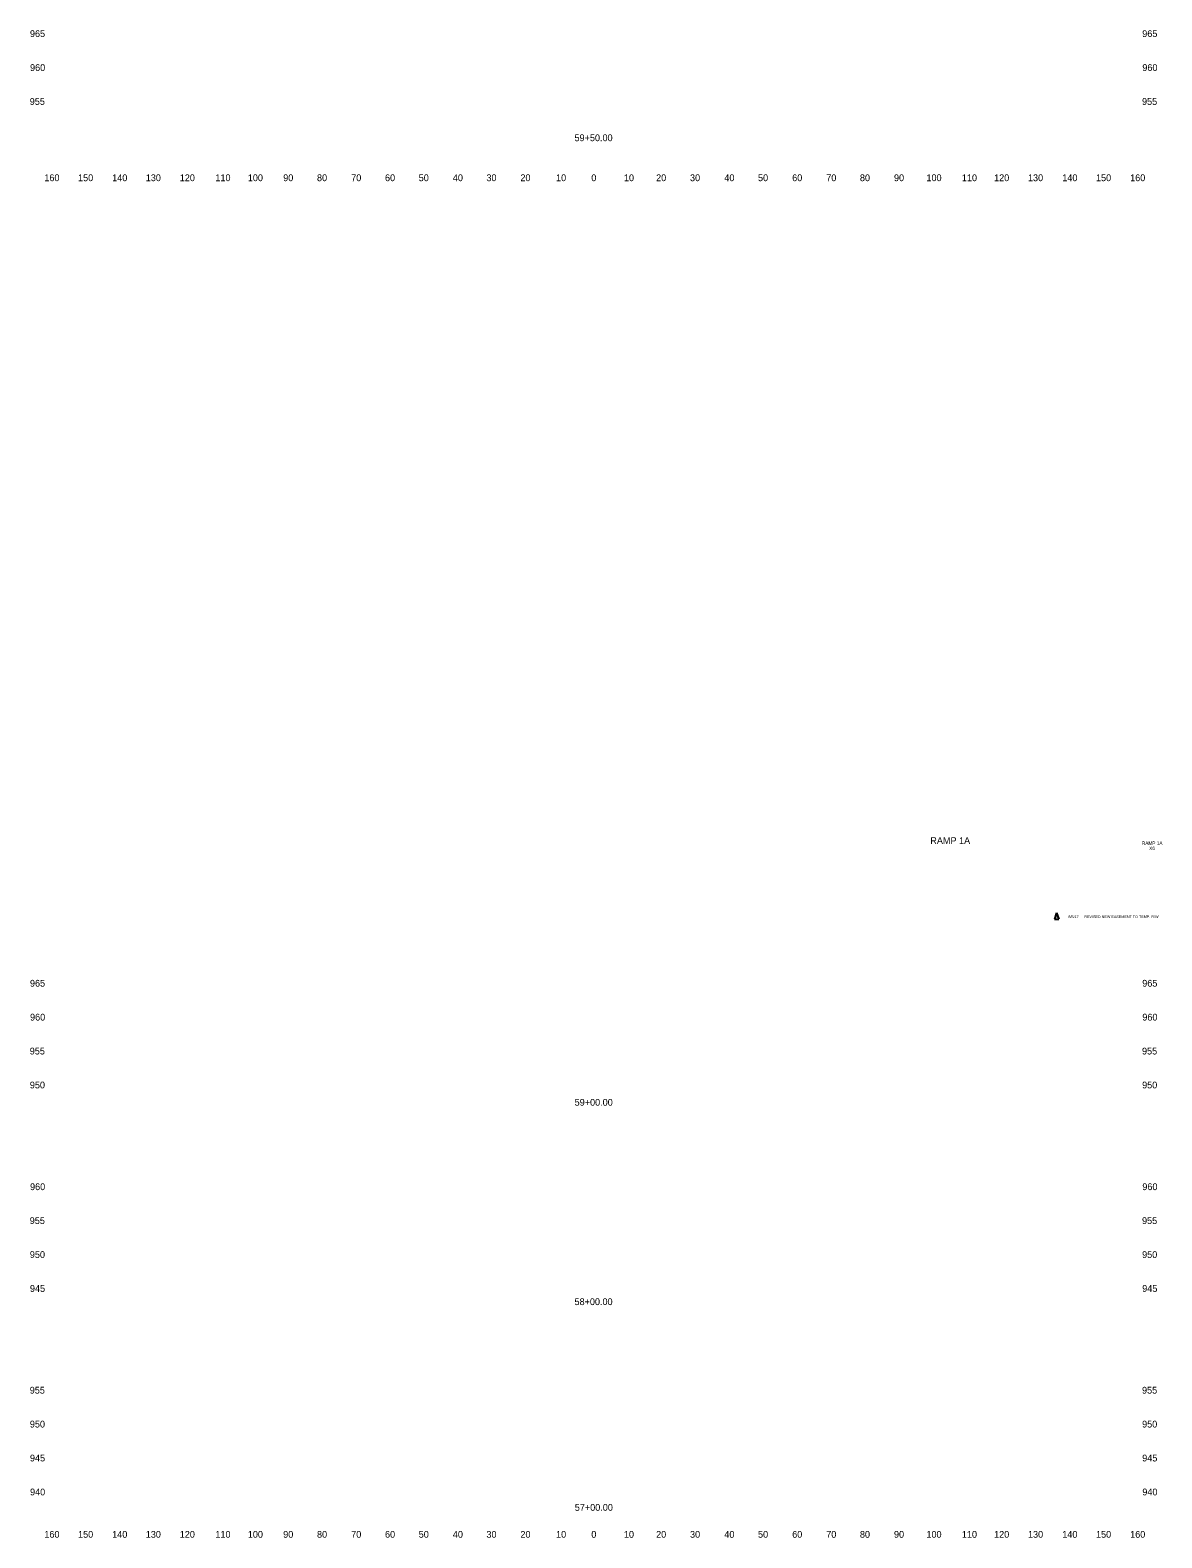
# Model space of a CAD drawing. Extents: x 4994 to 6873, y 4997 to 8804.
# Drawn here: x 4993.9 to 5327.4, y 6997.5 to 7442 of the extents above; entities that cross this region are included whole.
import ezdxf

# ---------------------------------------------------------------- set-up
doc = ezdxf.new("R2010")
doc.units = 0
for name, color, linetype in [('RD_SHT_ID', 7, 'Continuous'), ('RD_SHT_TX', 7, 'Continuous'), ('RD_XS_TX_Offset', 7, 'Continuous'), ('RD_XS_TX_Station', 7, 'Continuous')]:
    doc.layers.add(name, color=color, linetype=linetype)

msp = doc.modelspace()

# ---------------------------------------------------------------- linework, layer by layer
at = {"layer": 'RD_SHT_TX'}
for p, q in [((5296.41, 7181.77), (5295.76, 7179.94)), ((5295.76, 7179.94), (5297.05, 7179.94)), ((5296.41, 7181.77), (5297.05, 7179.94))]:
    msp.add_line(p, q, dxfattribs=at)

# ---------------------------------------------------------------- texts
at = {"layer": 'RD_SHT_ID'}
for s, height, p in [('RAMP 1A', 2, (5259.21, 7202.06)), ('RAMP 1A', 1, (5321.57, 7201.8)), ('X6', 1, (5323.71, 7200.3))]:
    msp.add_text(s, height=height, dxfattribs=at).set_placement(p)
at = {"layer": 'RD_SHT_TX'}
for s, p in [('1', (5296.41, 7180.24)), ('6/5/17', (5299.89, 7180.21)), ('REVISED NEW EASEMENT TO TEMP. R/W', (5304.6, 7180.21))]:
    msp.add_text(s, height=0.792, dxfattribs=at).set_placement(p)
at = {"layer": 'RD_XS_TX_Offset'}
for s, p in [('965', (4993.86, 7440)), ('965', (5321.66, 7440)), ('960', (4993.89, 7430)), ('960', (5321.69, 7430)), ('955', (4993.8, 7420)), ('955', (5321.6, 7420)), ('160', (4998.1, 7397.5)), ('150', (5008.04, 7397.5)), ('140', (5018.1, 7397.5)), ('130', (5027.99, 7397.5)), ('120', (5038.01, 7397.5)), ('110', (5048.51, 7397.5)), ('100', (5058.07, 7397.5)), ('90', (5068.5, 7397.5)), ('80', (5078.46, 7397.5)), ('70', (5088.54, 7397.5)), ('60', (5098.5, 7397.5)), ('50', (5108.43, 7397.5)), ('40', (5118.5, 7397.5)), ('30', (5128.39, 7397.5)), ('20', (5138.4, 7397.5)), ('10', (5148.91, 7397.5)), ('0', (5159.3, 7397.5)), ('0', (5159.3, 7397.5)), ('10', (5168.91, 7397.5)), ('20', (5178.4, 7397.5)), ('30', (5188.39, 7397.5)), ('40', (5198.5, 7397.5)), ('50', (5208.43, 7397.5)), ('60', (5218.5, 7397.5)), ('70', (5228.54, 7397.5)), ('80', (5238.46, 7397.5)), ('90', (5248.5, 7397.5)), ('100', (5258.07, 7397.5)), ('110', (5268.51, 7397.5)), ('120', (5278.01, 7397.5)), ('130', (5287.99, 7397.5)), ('140', (5298.1, 7397.5)), ('150', (5308.04, 7397.5)), ('160', (5318.1, 7397.5)), ('965', (4993.86, 7160)), ('965', (5321.66, 7160)), ('960', (4993.89, 7150)), ('960', (5321.69, 7150)), ('955', (4993.8, 7140)), ('955', (5321.6, 7140)), ('950', (4993.83, 7130)), ('950', (5321.63, 7130)), ('960', (4993.89, 7100)), ('960', (5321.69, 7100)), ('955', (4993.8, 7090)), ('955', (5321.6, 7090)), ('950', (4993.83, 7080)), ('950', (5321.63, 7080)), ('945', (4993.86, 7070)), ('945', (5321.66, 7070)), ('955', (4993.8, 7040)), ('955', (5321.6, 7040)), ('950', (4993.83, 7030)), ('950', (5321.63, 7030)), ('945', (4993.86, 7020)), ('945', (5321.66, 7020)), ('940', (4993.89, 7010)), ('940', (5321.69, 7010)), ('160', (4998.1, 6997.5)), ('150', (5008.04, 6997.5)), ('140', (5018.1, 6997.5)), ('130', (5027.99, 6997.5)), ('120', (5038.01, 6997.5)), ('110', (5048.51, 6997.5)), ('100', (5058.07, 6997.5)), ('90', (5068.5, 6997.5)), ('80', (5078.46, 6997.5)), ('70', (5088.54, 6997.5)), ('60', (5098.5, 6997.5)), ('50', (5108.43, 6997.5)), ('40', (5118.5, 6997.5)), ('30', (5128.39, 6997.5)), ('20', (5138.4, 6997.5)), ('10', (5148.91, 6997.5)), ('0', (5159.3, 6997.5)), ('0', (5159.3, 6997.5)), ('10', (5168.91, 6997.5)), ('20', (5178.4, 6997.5)), ('30', (5188.39, 6997.5)), ('40', (5198.5, 6997.5)), ('50', (5208.43, 6997.5)), ('60', (5218.5, 6997.5)), ('70', (5228.54, 6997.5)), ('80', (5238.46, 6997.5)), ('90', (5248.5, 6997.5)), ('100', (5258.07, 6997.5)), ('110', (5268.51, 6997.5)), ('120', (5278.01, 6997.5)), ('130', (5287.99, 6997.5)), ('140', (5298.1, 6997.5)), ('150', (5308.04, 6997.5)), ('160', (5318.1, 6997.5))]:
    msp.add_text(s, height=2, dxfattribs=at).set_placement(p)
at = {"layer": 'RD_XS_TX_Station'}
for s, p in [('59+50.00', (5154.35, 7409.29)), ('59+00.00', (5154.39, 7124.89)), ('58+00.00', (5154.35, 7066.1)), ('57+00.00', (5154.43, 7005.44))]:
    msp.add_text(s, height=2, dxfattribs=at).set_placement(p)

doc.saveas('drawing.dxf')
